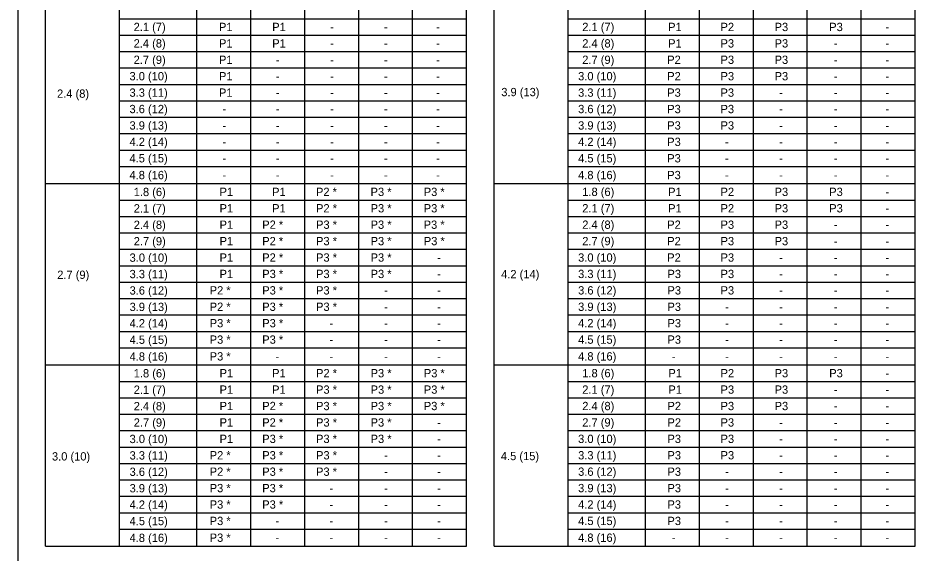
# Model space of a CAD drawing. Extents: x -1958 to 628, y -879 to 309.
# Drawn here: x -1077.4 to -752.7, y -78.6 to 115 of the extents above; entities that cross this region are included whole.
import ezdxf

# ---------------------------------------------------------------- set-up
doc = ezdxf.new("R2010")
doc.units = 0
doc.layers.add('1', color=7, linetype='Continuous')
doc.layers.add('2', color=7, linetype='Continuous')

msp = doc.modelspace()

# ---------------------------------------------------------------- linework, layer by layer
at = {"layer": '1'}
for p, q in [((-1077.39, 294.44), (-1077.39, -269.56)), ((-878.24, -76.15), (-878.24, 270.25)), ((-850.23, -76.15), (-850.23, 270.25)), ((-830.72, -76.15), (-830.72, 262.9)), ((-811.22, -76.15), (-811.22, 262.9)), ((-791.71, -76.15), (-791.71, 262.9)), ((-772.2, -76.15), (-772.2, 262.9)), ((-1067.39, -76.15), (-1067.39, 251.9)), ((-915.04, -76.15), (-915.04, 251.9)), ((-905.04, -76.15), (-905.04, 251.9)), ((-752.69, -76.15), (-752.69, 251.9)), ((-878.24, 114.74), (-752.69, 114.74)), ((-878.24, 108.8), (-752.69, 108.8)), ((-878.24, 102.86), (-752.69, 102.86)), ((-878.24, 96.92), (-752.69, 96.92)), ((-878.24, 90.98), (-752.69, 90.98)), ((-878.24, 85.04), (-752.69, 85.04)), ((-878.24, 79.1), (-752.69, 79.1)), ((-878.24, 73.16), (-752.69, 73.16)), ((-878.24, 67.22), (-752.69, 67.22)), ((-878.24, 61.28), (-752.69, 61.28)), ((-974.24, 55.07), (-938.6, 55.07)), ((-938.6, 55.07), (-915.04, 55.07)), ((-905.04, 55.07), (-752.69, 55.07)), ((-878.24, 49.13), (-752.69, 49.13)), ((-878.24, 43.19), (-752.69, 43.19)), ((-878.24, 37.25), (-752.69, 37.25)), ((-878.24, 31.31), (-752.69, 31.31)), ((-878.24, 25.37), (-752.69, 25.37)), ((-878.24, 19.43), (-752.69, 19.43)), ((-878.24, 13.49), (-752.69, 13.49)), ((-878.24, 7.55), (-752.69, 7.55)), ((-878.24, 1.61), (-752.69, 1.61)), ((-878.24, -4.33), (-752.69, -4.33)), ((-905.04, -10.54), (-752.69, -10.54)), ((-878.24, -16.48), (-752.69, -16.48)), ((-878.24, -22.42), (-752.69, -22.42)), ((-878.24, -28.36), (-752.69, -28.36)), ((-878.24, -34.3), (-752.69, -34.3)), ((-878.24, -40.24), (-752.69, -40.24)), ((-878.24, -46.18), (-752.69, -46.18)), ((-878.24, -52.12), (-752.69, -52.12)), ((-878.24, -58.06), (-752.69, -58.06)), ((-878.24, -64), (-752.69, -64)), ((-878.24, -69.94), (-752.69, -69.94)), ((-905.04, -76.15), (-752.69, -76.15))]:
    msp.add_line(p, q, dxfattribs=at)
at = {"layer": '2'}
for p, q in [((-1040.58, -76.15), (-1040.58, 251.9)), ((-1012.58, -76.15), (-1012.58, 251.9)), ((-993.07, -76.15), (-993.07, 251.9)), ((-973.56, -76.15), (-973.56, 251.9)), ((-954.05, -76.15), (-954.05, 251.9)), ((-934.55, -76.15), (-934.55, 251.9)), ((-1040.58, 114.74), (-915.04, 114.74)), ((-974.24, 114.74), (-938.6, 114.74)), ((-1040.58, 108.8), (-915.04, 108.8)), ((-974.24, 108.8), (-938.6, 108.8)), ((-1040.58, 102.86), (-915.04, 102.86)), ((-974.24, 102.86), (-938.6, 102.86)), ((-1040.58, 96.92), (-915.04, 96.92)), ((-974.24, 96.92), (-938.6, 96.92)), ((-1040.58, 90.98), (-915.04, 90.98)), ((-974.24, 90.98), (-938.6, 90.98)), ((-1040.58, 85.04), (-915.04, 85.04)), ((-1040.58, 79.1), (-915.04, 79.1)), ((-1040.58, 73.16), (-915.04, 73.16)), ((-1040.58, 67.22), (-915.04, 67.22)), ((-1040.58, 61.28), (-915.04, 61.28)), ((-1067.39, 55.07), (-915.04, 55.07)), ((-1040.58, 49.13), (-915.04, 49.13)), ((-1040.58, 43.19), (-915.04, 43.19)), ((-1040.58, 37.25), (-915.04, 37.25)), ((-1040.58, 31.31), (-915.04, 31.31)), ((-1040.58, 25.37), (-915.04, 25.37)), ((-1040.58, 19.43), (-915.04, 19.43)), ((-1040.58, 13.49), (-915.04, 13.49)), ((-1040.58, 7.55), (-915.04, 7.55)), ((-1040.58, 1.61), (-915.04, 1.61)), ((-1040.58, -4.33), (-915.04, -4.33)), ((-1067.39, -10.54), (-915.04, -10.54)), ((-1040.58, -16.48), (-915.04, -16.48)), ((-1040.58, -22.42), (-915.04, -22.42)), ((-1040.58, -28.36), (-915.04, -28.36)), ((-1040.58, -34.3), (-915.04, -34.3)), ((-1040.58, -40.24), (-915.04, -40.24)), ((-1040.58, -46.18), (-915.04, -46.18)), ((-1040.58, -52.12), (-915.04, -52.12)), ((-1040.58, -58.06), (-915.04, -58.06)), ((-1040.58, -64), (-915.04, -64)), ((-1040.58, -69.94), (-915.04, -69.94)), ((-974.24, -69.94), (-938.6, -69.94)), ((-1067.39, -76.15), (-915.04, -76.15))]:
    msp.add_line(p, q, dxfattribs=at)

# ---------------------------------------------------------------- texts
at = {"layer": '1'}
for s, p in [('2.1 (7)', (-873.14, 110.27)), ('P1', (-842.06, 110.27)), ('P2', (-823.1, 110.27)), ('P3', (-803.53, 110.27)), ('P3', (-783.76, 110.27)), ('-', (-763.44, 110.27)), ('2.4 (8)', (-873.14, 104.33)), ('P1', (-842.06, 104.33)), ('P3', (-823.1, 104.33)), ('P3', (-803.53, 104.33)), ('-', (-782.14, 104.33)), ('-', (-763.44, 104.33)), ('2.7 (9)', (-873.14, 98.39)), ('P2', (-842.4, 98.39)), ('P3', (-823.1, 98.39)), ('P3', (-803.53, 98.39)), ('-', (-782.14, 98.39)), ('-', (-763.44, 98.39)), ('3.0 (10)', (-874.64, 92.45)), ('P2', (-842.4, 92.45)), ('P3', (-823.1, 92.45)), ('P3', (-803.53, 92.45)), ('-', (-782.14, 92.45)), ('-', (-763.44, 92.45)), ('3.9 (13)', (-902.45, 86.71)), ('3.3 (11)', (-874.64, 86.51)), ('P3', (-842.4, 86.51)), ('P3', (-823.1, 86.51)), ('-', (-801.91, 86.51)), ('-', (-782.14, 86.51)), ('-', (-763.44, 86.51)), ('3.6 (12)', (-874.64, 80.57)), ('P3', (-842.4, 80.57)), ('P3', (-823.1, 80.57)), ('-', (-801.91, 80.57)), ('-', (-782.14, 80.57)), ('-', (-763.44, 80.57)), ('3.9 (13)', (-874.64, 74.63)), ('P3', (-842.4, 74.63)), ('P3', (-823.1, 74.63)), ('-', (-801.92, 74.63)), ('-', (-782.14, 74.63)), ('-', (-763.44, 74.63)), ('4.2 (14)', (-874.64, 68.69)), ('P3', (-842.4, 68.69)), ('-', (-821.48, 68.69)), ('-', (-801.92, 68.69)), ('-', (-782.14, 68.69)), ('-', (-763.44, 68.69)), ('4.5 (15)', (-874.64, 62.75)), ('P3', (-842.4, 62.75)), ('-', (-821.48, 62.75)), ('-', (-801.92, 62.75)), ('-', (-782.14, 62.75)), ('-', (-763.44, 62.75)), ('4.8 (16)', (-874.64, 56.68)), ('P3', (-842.4, 56.68)), ('-', (-821.48, 56.68)), ('-', (-801.92, 56.68)), ('-', (-782.14, 56.68)), ('-', (-763.44, 56.68)), ('1.8 (6)', (-873.14, 50.6)), ('P1', (-842.06, 50.6)), ('P2', (-823.1, 50.6)), ('P3', (-803.53, 50.6)), ('P3', (-783.76, 50.6)), ('-', (-763.44, 50.6)), ('2.1 (7)', (-873.14, 44.66)), ('P1', (-842.06, 44.66)), ('P2', (-823.09, 44.66)), ('P3', (-803.53, 44.66)), ('P3', (-783.76, 44.66)), ('-', (-763.44, 44.66)), ('2.4 (8)', (-873.14, 38.72)), ('P2', (-842.4, 38.72)), ('P3', (-823.09, 38.72)), ('P3', (-803.53, 38.72)), ('-', (-782.14, 38.72)), ('-', (-763.44, 38.72)), ('2.7 (9)', (-873.14, 32.78)), ('P2', (-842.4, 32.78)), ('P3', (-823.09, 32.78)), ('P3', (-803.53, 32.78)), ('-', (-782.14, 32.78)), ('-', (-763.44, 32.78)), ('3.0 (10)', (-874.64, 26.84)), ('P2', (-842.4, 26.84)), ('P3', (-823.09, 26.84)), ('-', (-801.92, 26.84)), ('-', (-782.14, 26.84)), ('-', (-763.44, 26.84)), ('4.2 (14)', (-902.5, 20.82)), ('3.3 (11)', (-874.64, 20.9)), ('P3', (-842.31, 20.9)), ('P3', (-823.09, 20.9)), ('-', (-801.92, 20.9)), ('-', (-782.14, 20.9)), ('-', (-763.44, 20.9)), ('3.6 (12)', (-874.64, 14.96)), ('P3', (-842.31, 14.96)), ('P3', (-823.09, 14.96)), ('-', (-801.92, 14.96)), ('-', (-782.14, 14.96)), ('-', (-763.44, 14.96)), ('3.9 (13)', (-874.64, 9.02)), ('P3', (-842.31, 9.02)), ('-', (-821.47, 9.02)), ('-', (-801.92, 9.02)), ('-', (-782.13, 9.02)), ('-', (-763.44, 9.02)), ('4.2 (14)', (-874.64, 3.08)), ('P3', (-842.31, 3.08)), ('-', (-821.47, 3.08)), ('-', (-801.92, 3.08)), ('-', (-782.13, 3.08)), ('-', (-763.44, 3.08)), ('4.5 (15)', (-874.64, -2.86)), ('P3', (-842.31, -2.86)), ('-', (-821.47, -2.86)), ('-', (-801.92, -2.86)), ('-', (-782.13, -2.86)), ('-', (-763.44, -2.86)), ('4.8 (16)', (-874.64, -8.93)), ('-', (-840.7, -8.93)), ('-', (-821.47, -8.93)), ('-', (-801.92, -8.93)), ('-', (-782.13, -8.93)), ('-', (-763.44, -8.93)), ('1.8 (6)', (-873.14, -15.01)), ('P1', (-841.97, -15.01)), ('P2', (-823.09, -15.01)), ('P3', (-803.53, -15.01)), ('P3', (-783.75, -15.01)), ('-', (-763.44, -15.01)), ('2.1 (7)', (-873.14, -20.95)), ('P1', (-841.97, -20.95)), ('P3', (-823.09, -20.95)), ('P3', (-803.53, -20.95)), ('-', (-782.13, -20.95)), ('-', (-763.44, -20.95)), ('2.4 (8)', (-873.14, -26.89)), ('P2', (-842.31, -26.89)), ('P3', (-823.09, -26.89)), ('P3', (-803.53, -26.89)), ('-', (-782.13, -26.89)), ('-', (-763.44, -26.89)), ('2.7 (9)', (-873.14, -32.83)), ('P2', (-842.31, -32.83)), ('P3', (-823.09, -32.83)), ('-', (-801.92, -32.83)), ('-', (-782.13, -32.83)), ('-', (-763.44, -32.83)), ('3.0 (10)', (-874.64, -38.77)), ('P3', (-842.31, -38.77)), ('P3', (-823.09, -38.77)), ('-', (-801.92, -38.77)), ('-', (-782.13, -38.77)), ('-', (-763.44, -38.77)), ('4.5 (15)', (-902.59, -44.98)), ('3.3 (11)', (-874.64, -44.71)), ('P3', (-842.31, -44.71)), ('P3', (-823.09, -44.71)), ('-', (-801.92, -44.71)), ('-', (-782.13, -44.71)), ('-', (-763.44, -44.71)), ('3.6 (12)', (-874.64, -50.65)), ('P3', (-842.31, -50.65)), ('-', (-821.47, -50.65)), ('-', (-801.92, -50.65)), ('-', (-782.13, -50.65)), ('-', (-763.44, -50.65)), ('3.9 (13)', (-874.64, -56.59)), ('P3', (-842.31, -56.59)), ('-', (-821.47, -56.59)), ('-', (-801.92, -56.59)), ('-', (-782.13, -56.59)), ('-', (-763.44, -56.59)), ('4.2 (14)', (-874.64, -62.53)), ('P3', (-842.31, -62.53)), ('-', (-821.47, -62.53)), ('-', (-801.92, -62.53)), ('-', (-782.13, -62.53)), ('-', (-763.44, -62.53)), ('4.5 (15)', (-874.64, -68.47)), ('P3', (-842.31, -68.47)), ('-', (-821.47, -68.47)), ('-', (-801.92, -68.47)), ('-', (-782.13, -68.47)), ('-', (-763.44, -68.47)), ('4.8 (16)', (-874.64, -74.54)), ('-', (-840.7, -74.54)), ('-', (-821.47, -74.54)), ('-', (-801.92, -74.54)), ('-', (-782.13, -74.54)), ('-', (-763.44, -74.54))]:
    msp.add_text(s, height=3, dxfattribs=at).set_placement(p)
at = {"layer": '2'}
for s, p in [('2.1 (7)', (-1035.51, 110.27)), ('P1', (-1004.62, 110.27)), ('P1', (-985.35, 110.27)), ('-', (-964.36, 110.27)), ('-', (-944.91, 110.27)), ('-', (-925.97, 110.27)), ('2.4 (8)', (-1035.51, 104.33)), ('P1', (-1004.62, 104.33)), ('P1', (-985.35, 104.33)), ('-', (-964.36, 104.33)), ('-', (-944.91, 104.33)), ('-', (-925.97, 104.33)), ('2.7 (9)', (-1035.51, 98.39)), ('P1', (-1004.62, 98.39)), ('-', (-984.07, 98.39)), ('-', (-964.36, 98.39)), ('-', (-944.91, 98.39)), ('-', (-925.97, 98.39)), ('3.0 (10)', (-1037.01, 92.45)), ('P1', (-1004.62, 92.45)), ('-', (-984.07, 92.45)), ('-', (-964.36, 92.45)), ('-', (-944.91, 92.45)), ('-', (-925.97, 92.45)), ('2.4 (8)', (-1063.23, 86.14)), ('3.3 (11)', (-1037.01, 86.51)), ('P1', (-1004.62, 86.51)), ('-', (-984.07, 86.51)), ('-', (-964.36, 86.51)), ('-', (-944.91, 86.51)), ('-', (-925.97, 86.51)), ('3.6 (12)', (-1037.01, 80.57)), ('-', (-1003.34, 80.57)), ('-', (-984.07, 80.57)), ('-', (-964.36, 80.57)), ('-', (-944.91, 80.57)), ('-', (-925.97, 80.57)), ('3.9 (13)', (-1037.01, 74.63)), ('-', (-1003.34, 74.63)), ('-', (-984.07, 74.63)), ('-', (-964.36, 74.63)), ('-', (-944.91, 74.63)), ('-', (-925.97, 74.63)), ('4.2 (14)', (-1037.01, 68.69)), ('-', (-1003.34, 68.69)), ('-', (-984.07, 68.69)), ('-', (-964.36, 68.69)), ('-', (-944.91, 68.69)), ('-', (-925.97, 68.69)), ('4.5 (15)', (-1037.01, 62.75)), ('-', (-1003.34, 62.75)), ('-', (-984.07, 62.75)), ('-', (-964.36, 62.75)), ('-', (-944.91, 62.75)), ('-', (-925.97, 62.75)), ('4.8 (16)', (-1037.01, 56.68)), ('-', (-1003.34, 56.68)), ('-', (-984.07, 56.68)), ('-', (-964.36, 56.68)), ('-', (-944.91, 56.68)), ('-', (-925.97, 56.68)), ('1.8 (6)', (-1035.48, 50.56)), ('P1', (-1004.42, 50.6)), ('P1', (-985.39, 50.6)), ('P2 *', (-969.51, 50.6)), ('P3 *', (-949.76, 50.6)), ('P3 *', (-930.51, 50.6)), ('2.1 (7)', (-1035.48, 44.62)), ('P1', (-1004.41, 44.66)), ('P1', (-985.39, 44.66)), ('P2 *', (-969.49, 44.66)), ('P3 *', (-949.74, 44.66)), ('P3 *', (-930.51, 44.66)), ('2.4 (8)', (-1035.48, 38.68)), ('P1', (-1004.41, 38.72)), ('P2 *', (-988.97, 38.72)), ('P3 *', (-969.49, 38.72)), ('P3 *', (-949.74, 38.72)), ('P3 *', (-930.54, 38.72)), ('2.7 (9)', (-1035.48, 32.74)), ('P1', (-1004.41, 32.78)), ('P2 *', (-988.97, 32.78)), ('P3 *', (-969.49, 32.78)), ('P3 *', (-949.74, 32.78)), ('P3 *', (-930.49, 32.78)), ('3.0 (10)', (-1036.98, 26.8)), ('P1', (-1004.41, 26.84)), ('P2 *', (-988.97, 26.84)), ('P3 *', (-969.49, 26.84)), ('P3 *', (-949.74, 26.84)), ('-', (-925.64, 26.84)), ('2.7 (9)', (-1063.16, 20.6)), ('3.3 (11)', (-1036.98, 20.86)), ('P1', (-1004.41, 20.9)), ('P3 *', (-988.97, 20.9)), ('P3 *', (-969.49, 20.9)), ('P3 *', (-949.74, 20.9)), ('-', (-925.64, 20.9)), ('3.6 (12)', (-1036.98, 14.92)), ('P2 *', (-1007.98, 14.96)), ('P3 *', (-988.97, 14.96)), ('P3 *', (-969.49, 14.96)), ('-', (-944.89, 14.96)), ('-', (-925.64, 14.96)), ('3.9 (13)', (-1036.98, 8.98)), ('P2 *', (-1007.98, 9.02)), ('P3 *', (-988.97, 9.02)), ('P3 *', (-969.49, 9.02)), ('-', (-944.89, 9.02)), ('-', (-925.64, 9.02)), ('4.2 (14)', (-1036.98, 3.04)), ('P3 *', (-1007.98, 3.08)), ('P3 *', (-988.97, 3.08)), ('-', (-964.64, 3.08)), ('-', (-944.89, 3.08)), ('-', (-925.64, 3.08)), ('4.5 (15)', (-1036.98, -2.9)), ('P3 *', (-1007.98, -2.86)), ('P3 *', (-988.97, -2.86)), ('-', (-964.64, -2.86)), ('-', (-944.89, -2.86)), ('-', (-925.64, -2.86)), ('4.8 (16)', (-1036.98, -8.98)), ('P3 *', (-1007.98, -8.93)), ('-', (-984.12, -8.93)), ('-', (-964.64, -8.93)), ('-', (-944.89, -8.93)), ('-', (-925.64, -8.93)), ('1.8 (6)', (-1035.48, -15.05)), ('P1', (-1004.41, -15.01)), ('P1', (-985.39, -15.01)), ('P2 *', (-969.49, -15.01)), ('P3 *', (-949.74, -15.01)), ('P3 *', (-930.49, -15.01)), ('2.1 (7)', (-1035.48, -20.99)), ('P1', (-1004.41, -20.95)), ('P1', (-985.39, -20.95)), ('P3 *', (-969.49, -20.95)), ('P3 *', (-949.74, -20.95)), ('P3 *', (-930.49, -20.95)), ('2.4 (8)', (-1035.48, -26.93)), ('P1', (-1004.41, -26.89)), ('P2 *', (-988.97, -26.89)), ('P3 *', (-969.49, -26.89)), ('P3 *', (-949.74, -26.89)), ('P3 *', (-930.49, -26.89)), ('2.7 (9)', (-1035.48, -32.87)), ('P1', (-1004.41, -32.83)), ('P2 *', (-988.97, -32.83)), ('P3 *', (-969.49, -32.83)), ('P3 *', (-949.74, -32.83)), ('-', (-925.64, -32.83)), ('3.0 (10)', (-1036.98, -38.81)), ('P1', (-1004.41, -38.77)), ('P3 *', (-988.97, -38.77)), ('P3 *', (-969.49, -38.77)), ('P3 *', (-949.74, -38.77)), ('-', (-925.64, -38.77)), ('3.0 (10)', (-1065.07, -45.11)), ('3.3 (11)', (-1036.98, -44.75)), ('P2 *', (-1007.98, -44.71)), ('P3 *', (-988.97, -44.71)), ('P3 *', (-969.49, -44.71)), ('-', (-944.89, -44.71)), ('-', (-925.64, -44.71)), ('3.6 (12)', (-1036.98, -50.69)), ('P2 *', (-1007.98, -50.65)), ('P3 *', (-988.97, -50.65)), ('P3 *', (-969.49, -50.65)), ('-', (-944.89, -50.65)), ('-', (-925.64, -50.65)), ('3.9 (13)', (-1036.98, -56.63)), ('P3 *', (-1007.98, -56.59)), ('P3 *', (-988.97, -56.59)), ('-', (-964.64, -56.59)), ('-', (-944.89, -56.59)), ('-', (-925.64, -56.59)), ('4.2 (14)', (-1036.98, -62.57)), ('P3 *', (-1007.98, -62.53)), ('P3 *', (-988.97, -62.53)), ('-', (-964.64, -62.53)), ('-', (-944.89, -62.53)), ('-', (-925.64, -62.53)), ('4.5 (15)', (-1036.98, -68.51)), ('P3 *', (-1007.98, -68.47)), ('-', (-984.12, -68.47)), ('-', (-964.64, -68.47)), ('-', (-944.89, -68.47)), ('-', (-925.64, -68.47)), ('4.8 (16)', (-1036.98, -74.59)), ('P3 *', (-1007.98, -74.54)), ('-', (-984.12, -74.54)), ('-', (-964.64, -74.54)), ('-', (-944.89, -74.54)), ('-', (-925.64, -74.54))]:
    msp.add_text(s, height=3, dxfattribs=at).set_placement(p)

doc.saveas('drawing.dxf')
